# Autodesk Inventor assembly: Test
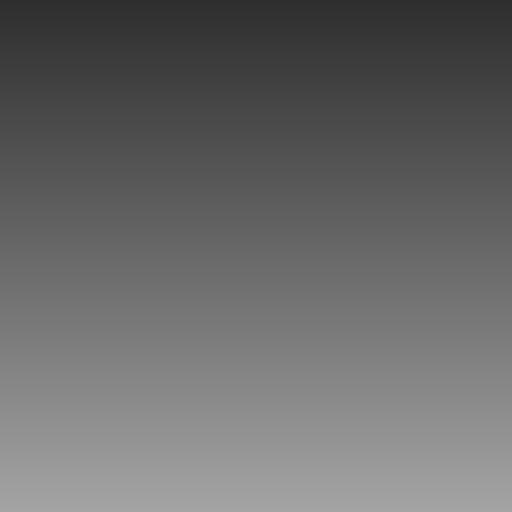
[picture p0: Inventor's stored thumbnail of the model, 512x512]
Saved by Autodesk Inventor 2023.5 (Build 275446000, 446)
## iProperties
Created: 2023-06
Document SubType Name: Assembly
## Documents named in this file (1)
- D:\AB\Inventor\Test.iam
